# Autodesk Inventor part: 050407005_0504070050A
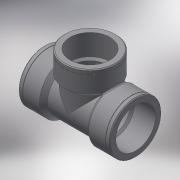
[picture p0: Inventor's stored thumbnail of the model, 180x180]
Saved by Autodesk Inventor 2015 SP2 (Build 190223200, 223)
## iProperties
Created: 2017-05
Part Number: 050407005_0504070050A
Material: Generic
Description: PLASSON THREADED TEE 1/2"
Document SubType Name: Modeling
Designer: KIM
Density: 1 g/cm^3
Appearance: Default
Author: KIM
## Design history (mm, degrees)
derived "050407.ipt"
feature "Solid1::050407.ipt"
tag "TaggingFeature1"
body "Solid1"
other parameters: "d0" = 32, "d2" = 0.5, "d3" = 0.5, "d4" = 24.2203, "d5" = 18.631, "d6" = 18, "d7" = 135 deg, "d8" = 20.7, "d9" = 3.45, "d19" = 0.37262, "d27" = 18, "d30" = 16.7679, "d31" = 20.4941, "d33" = 180 deg, "d39" = 0, "d45" = 0, "d46" = 20.4941, "d48" = 0, "d50" = 0, "d51" = 0.55893, "Rp_" = 18.631, "H_" = 64, "l_2" = 18
